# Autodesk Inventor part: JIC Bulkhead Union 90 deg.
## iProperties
Category: Hydraulics
Company: Mountain Blue Industries Ltd.
Title: JIC Bulkhead Union 90 deg.
Subject: Hydraulic Adapters
Author: QBZ
Shininess: 64.0
Angle Display Precision: 2
Document Length Units: 11272
Document Angle Units: 11286
Document Time Units: 11279
Document Mass Units: 11290
Document Length Units Precision: 3
Document Angle Units Precision: 2
Compacted: True
PropertySet Name: _Private Model Information
Created: 2002-04
Part Number: 2043-8-8S
Material: Steel, Mild
Catalog Web Link: http://www.aeroquip.com
Description: JIC Bulkhead 90 -8
Document SubType Name: Modeling
Designer: QBZ
Control State: 0
Master: False
Checked Out: False
PropertySet Name: Design Tracking Control
Density: 0.0
Volumn: 0.0
Area: 0.0
PropertySet Name: Model Information
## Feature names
1. Extrusion1
2. Extrusion2
3. Revolution1
4. Revolution2
5. Revolution3
6. Sweep1
7. Fillet1
